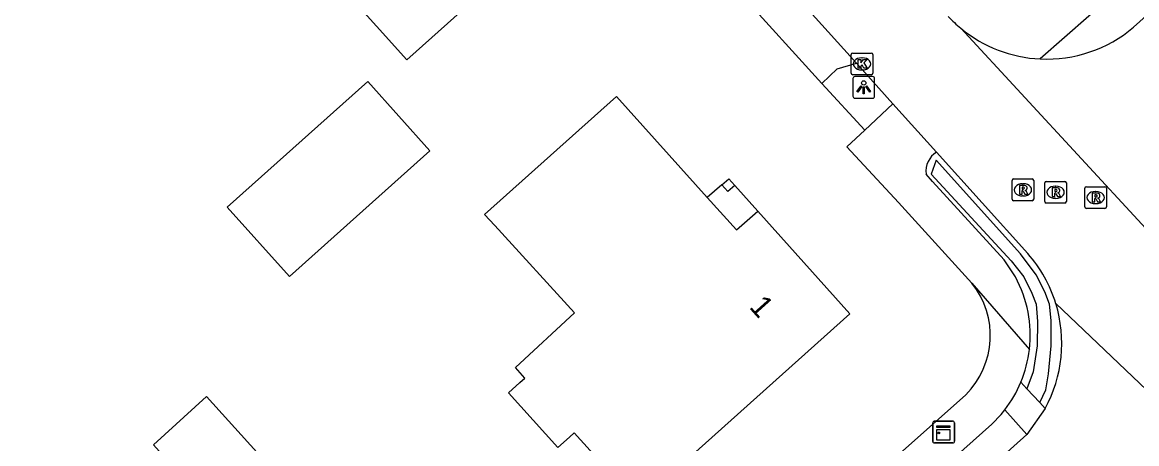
# Model space of a CAD drawing. Extents: x 163268 to 164360, y 381529 to 382285.
# Drawn here: x 163951.8 to 164003, y 381738.3 to 381757.6 of the extents above; entities that cross this region are included whole.
import ezdxf

# ---------------------------------------------------------------- set-up
doc = ezdxf.new("R2010")
doc.units = 0
for name, color, linetype in [('IMGEO_Haag', 7, 'Continuous'), ('IMGEO_Kast', 7, 'Continuous'), ('IMGEO_Kolk', 7, 'Continuous'), ('IMGEO_Lichtpunt', 7, 'Continuous'), ('IMGEO_Pand', 7, 'Continuous'), ('IMGEO_Pand_nummerreeks', 7, 'Continuous'), ('IMGEO_Pand_overbouw', 7, 'Continuous'), ('IMGEO_Rijbaan_lokaal_open', 7, 'Continuous'), ('IMGEO_Rioolput', 7, 'Continuous'), ('IMGEO_Voetpad_halfverhard', 7, 'Continuous'), ('IMGEO_Voetpad_open', 7, 'Continuous')]:
    doc.layers.add(name, color=color, linetype=linetype)

msp = doc.modelspace()

# ---------------------------------------------------------------- linework, layer by layer
at = {"layer": 'IMGEO_Haag'}
msp.add_lwpolyline([(163998.511, 381740.158), (163998.792, 381740.742), (163998.918, 381741.476), (163999.044, 381742.778), (163999.044, 381743.932), (163998.96, 381744.688), (163998.74, 381745.26), (163998.341, 381746.036), (163997.623, 381747.001), (163993.75, 381751.311), (163993.518, 381750.663), (163997.204, 381746.68), (163997.774, 381745.947), (163998.152, 381745.191), (163998.351, 381744.688), (163998.414, 381743.89), (163998.393, 381742.778), (163998.205, 381741.581), (163997.921, 381740.797)], dxfattribs=at)
at = {"layer": 'IMGEO_Kast'}
for p, q in [((163993.592, 381738.378), (163993.592, 381739.219)), ((163993.592, 381739.219), (163993.592, 381738.378)), ((163993.667, 381739.303), (163994.508, 381739.303)), ((163994.508, 381739.303), (163993.667, 381739.303)), ((163994.592, 381739.228), (163994.592, 381738.387)), ((163994.592, 381738.387), (163994.592, 381739.228)), ((163994.517, 381738.303), (163993.676, 381738.303)), ((163993.676, 381738.303), (163994.517, 381738.303))]:
    msp.add_line(p, q, dxfattribs=at)
for points in [[(163993.787, 381739.093), (163994.387, 381739.093), (163994.387, 381739.008), (163993.787, 381739.008), (163993.787, 381739.093)], [(163993.787, 381738.918), (163994.387, 381738.918), (163994.387, 381738.429), (163993.787, 381738.429), (163993.787, 381738.918)]]:
    msp.add_lwpolyline(points, dxfattribs=at)
msp.add_circle((163993.871, 381738.767), 0.0377, dxfattribs=at)
for centre, start, end in [((163993.67, 381739.225), 92.4484, 184.2845), ((163993.67, 381739.225), 92.4484, 184.2845), ((163994.514, 381739.225), 2.4484, 94.2845), ((163994.514, 381739.225), 2.4484, 94.2845), ((163993.67, 381738.381), 182.4484, 274.2845), ((163993.67, 381738.381), 182.4484, 274.2845), ((163994.514, 381738.381), 272.4484, 4.2845), ((163994.514, 381738.381), 272.4484, 4.2845)]:
    msp.add_arc(centre, 0.0779, start, end, dxfattribs=at)
at = {"layer": 'IMGEO_Kolk'}
for p, q in [((163989.84, 381755.309), (163989.84, 381756.161)), ((163989.915, 381756.235), (163990.767, 381756.235)), ((163990.328, 381756.015), (163990.353, 381756.015)), ((163990.841, 381756.161), (163990.841, 381755.309)), ((163990.351, 381755.455), (163990.326, 381755.455)), ((163990.767, 381755.235), (163989.915, 381755.235))]:
    msp.add_line(p, q, dxfattribs=at)
for points in [[(163989.84, 381755.309), (163989.84, 381756.161)], [(163989.915, 381756.235), (163990.767, 381756.235)], [(163990.161, 381755.935), (163990.284, 381755.935), (163990.284, 381755.784), (163990.414, 381755.935), (163990.578, 381755.935), (163990.432, 381755.784), (163990.585, 381755.535), (163990.433, 381755.535), (163990.348, 381755.699), (163990.284, 381755.632), (163990.284, 381755.535), (163990.161, 381755.535), (163990.161, 381755.935)], [(163990.841, 381756.161), (163990.841, 381755.309)], [(163990.767, 381755.235), (163989.915, 381755.235)]]:
    msp.add_lwpolyline(points, dxfattribs=at)
for centre, start, end in [((163989.917, 381756.159), 91.552, 178.448), ((163989.917, 381756.159), 91.552, 178.448), ((163990.765, 381756.159), 1.552, 88.448), ((163990.765, 381756.159), 1.552, 88.448), ((163989.917, 381755.311), 181.552, 268.448), ((163989.917, 381755.311), 181.552, 268.448), ((163990.765, 381755.311), 271.552, 358.448), ((163990.765, 381755.311), 271.552, 358.448)]:
    msp.add_arc(centre, 0.0765, start, end, dxfattribs=at)
for centre, major_axis, ratio, start_param, end_param in [((163990.327, 381755.735), (-0.387, 0.002), 0.722429, 4.712389, 7.853982), ((163990.352, 381755.735), (-0.39, 0.002), 0.717154, 1.570796, 4.712389)]:
    msp.add_ellipse(centre, major_axis=major_axis, ratio=ratio, start_param=start_param, end_param=end_param, dxfattribs=at)
at = {"layer": 'IMGEO_Lichtpunt'}
for p, q in [((163989.926, 381755.06), (163989.926, 381754.253)), ((163989.926, 381755.06), (163989.926, 381754.253)), ((163990.828, 381755.155), (163990.02, 381755.155)), ((163990.828, 381755.155), (163990.02, 381755.155)), ((163990.922, 381754.253), (163990.922, 381755.06)), ((163990.922, 381754.253), (163990.922, 381755.06)), ((163990.02, 381754.159), (163990.828, 381754.159)), ((163990.02, 381754.159), (163990.828, 381754.159))]:
    msp.add_line(p, q, dxfattribs=at)
for points in [[(163990.3, 381754.724), (163990.339, 381754.696), (163990.151, 381754.434), (163990.113, 381754.461), (163990.3, 381754.724)], [(163990.402, 381754.676), (163990.449, 381754.676), (163990.449, 381754.354), (163990.402, 381754.354), (163990.402, 381754.676)], [(163990.512, 381754.696), (163990.55, 381754.723), (163990.737, 381754.461), (163990.698, 381754.433), (163990.512, 381754.696)]]:
    msp.add_lwpolyline(points, dxfattribs=at)
msp.add_circle((163990.425, 381754.858), 0.0994, dxfattribs=at)
for centre, start, end in [((163990.02, 381755.06), 90, 180), ((163990.02, 381755.06), 90, 180), ((163990.828, 381755.06), 0, 90), ((163990.828, 381755.06), 0, 90), ((163990.02, 381754.253), 180, 270), ((163990.02, 381754.253), 180, 270), ((163990.828, 381754.253), 270, 0), ((163990.828, 381754.253), 270, 360)]:
    msp.add_arc(centre, 0.0946, start, end, dxfattribs=at)
at = {"layer": 'IMGEO_Pand'}
for points in [[(163965.246, 381760.582), (163963.764, 381759.239), (163959.258, 381764.212), (163960.741, 381765.555), (163960.075, 381766.289), (163965.567, 381771.211), (163974.889, 381760.835), (163969.419, 381755.929), (163965.246, 381760.582)], [(163961.17, 381749.144), (163967.63, 381754.927), (163970.487, 381751.735), (163964.028, 381745.953), (163961.17, 381749.144)], [(163979.064, 381754.234), (163983.233, 381749.598), (163984.57, 381748.111), (163985.554, 381748.969), (163989.791, 381744.248), (163980.063, 381735.515), (163977.118, 381738.774), (163976.899, 381738.577), (163976.361, 381738.091), (163974.092, 381740.608), (163974.62, 381741.084), (163974.849, 381741.291), (163974.416, 381741.778), (163977.13, 381744.283), (163973.47, 381748.297), (163972.999, 381748.813), (163979.064, 381754.234)], [(163983.902, 381750.181), (163984.219, 381750.457), (163984.499, 381750.144), (163984.183, 381749.868), (163983.902, 381750.181)], [(163957.785, 381738.222), (163960.225, 381740.447), (163964.847, 381735.323), (163965.172, 381735.604), (163965.852, 381734.818), (163965.574, 381734.523), (163966.36, 381733.631), (163963.849, 381731.446), (163957.785, 381738.222)]]:
    msp.add_lwpolyline(points, dxfattribs=at)
at = {"layer": 'IMGEO_Pand_overbouw'}
msp.add_lwpolyline([(163984.499, 381750.144), (163984.183, 381749.868), (163983.902, 381750.181), (163983.233, 381749.598), (163984.57, 381748.111), (163985.554, 381748.969)], close=True, dxfattribs=at)
at = {"layer": 'IMGEO_Rijbaan_lokaal_open'}
for points in [[(164002.826, 381757.42), (164010.255, 381764.1)], [(163985.739, 381760.594), (163990.087, 381755.766)], [(164005.983, 381745.357), (163994.884, 381757.372)], [(163990.087, 381755.766), (163991.765, 381753.902)], [(163993.771, 381751.675), (163991.765, 381753.902)], [(163993.771, 381751.675), (163997.969, 381747.012)], [(163999.252, 381744.71), (164008.883, 381735.535)], [(163998.759, 381739.889), (163997.915, 381738.698)], [(163997.915, 381738.698), (163942.403, 381688.848)]]:
    msp.add_lwpolyline(points, dxfattribs=at)
for centre, radius, start, end in [((163998.916, 381762.242), 6.323, 223.212, 230.3774), ((163998.831, 381762.16), 6.205, 230.5017, 267.2972), ((163998.826, 381762.149), 6.194, 267.334, 310.224), ((163993.259, 381742.878), 6.266, 16.9941, 41.2714), ((163993.273, 381742.886), 6.251, 331.3545, 16.9679)]:
    msp.add_arc(centre, radius, start, end, dxfattribs=at)
at = {"layer": 'IMGEO_Rioolput'}
for p, q in [((163997.238, 381749.518), (163997.238, 381750.37)), ((163997.313, 381750.444), (163998.165, 381750.444)), ((163997.726, 381750.224), (163997.751, 381750.224)), ((163998.239, 381750.37), (163998.239, 381749.518)), ((163998.739, 381749.407), (163998.739, 381750.259)), ((163998.814, 381750.333), (163999.666, 381750.333)), ((163999.74, 381750.259), (163999.74, 381749.407)), ((163997.749, 381749.664), (163997.724, 381749.664)), ((163999.227, 381750.113), (163999.252, 381750.113)), ((164000.581, 381749.162), (164000.581, 381750.014)), ((164000.656, 381750.088), (164001.508, 381750.088)), ((164001.069, 381749.868), (164001.094, 381749.868)), ((164001.582, 381750.014), (164001.582, 381749.162)), ((163998.165, 381749.444), (163997.313, 381749.444)), ((163999.666, 381749.333), (163998.814, 381749.333)), ((163999.25, 381749.553), (163999.225, 381749.553)), ((164001.092, 381749.308), (164001.067, 381749.308)), ((164001.508, 381749.088), (164000.656, 381749.088))]:
    msp.add_line(p, q, dxfattribs=at)
for points in [[(163997.238, 381749.518), (163997.238, 381750.37)], [(163997.313, 381750.444), (163998.165, 381750.444)], [(163997.827, 381750.142), (163997.575, 381750.144), (163997.575, 381749.744)], [(163998.239, 381750.37), (163998.239, 381749.518)], [(163998.739, 381749.407), (163998.739, 381750.259)], [(163998.814, 381750.333), (163999.666, 381750.333)], [(163999.74, 381750.259), (163999.74, 381749.407)], [(163997.575, 381749.744), (163997.699, 381749.744), (163997.699, 381749.906), (163997.71, 381749.906)], [(163997.753, 381750.063), (163997.699, 381750.063), (163997.699, 381749.982)], [(163997.699, 381749.982), (163997.751, 381749.982)], [(163997.757, 381749.877), (163997.828, 381749.744), (163997.968, 381749.744), (163997.903, 381749.87)], [(163999.328, 381750.031), (163999.076, 381750.033), (163999.076, 381749.633)], [(163999.076, 381749.633), (163999.2, 381749.633), (163999.2, 381749.795), (163999.211, 381749.795)], [(163999.254, 381749.952), (163999.2, 381749.952), (163999.2, 381749.871)], [(163999.2, 381749.871), (163999.252, 381749.871)], [(163999.258, 381749.766), (163999.329, 381749.633), (163999.469, 381749.633), (163999.404, 381749.759)], [(164000.581, 381749.162), (164000.581, 381750.014)], [(164000.656, 381750.088), (164001.508, 381750.088)], [(164001.17, 381749.786), (164000.918, 381749.788), (164000.918, 381749.388)], [(164001.096, 381749.707), (164001.042, 381749.707), (164001.042, 381749.626)], [(164001.042, 381749.626), (164001.094, 381749.626)], [(164001.582, 381750.014), (164001.582, 381749.162)], [(163998.165, 381749.444), (163997.313, 381749.444)], [(163999.666, 381749.333), (163998.814, 381749.333)], [(164000.918, 381749.388), (164001.042, 381749.388), (164001.042, 381749.55), (164001.053, 381749.55)], [(164001.1, 381749.521), (164001.171, 381749.388), (164001.311, 381749.388), (164001.246, 381749.514)], [(164001.508, 381749.088), (164000.656, 381749.088)]]:
    msp.add_lwpolyline(points, dxfattribs=at)
for centre, radius, start, end in [((163997.315, 381750.368), 0.0765, 91.552, 178.448), ((163997.315, 381750.368), 0.0765, 91.552, 178.448), ((163997.826, 381750.032), 0.109, 350.3612, 89.416), ((163998.163, 381750.368), 0.0765, 1.552, 88.448), ((163998.163, 381750.368), 0.0765, 1.552, 88.448), ((163998.816, 381750.257), 0.0765, 91.552, 178.448), ((163998.816, 381750.257), 0.0765, 91.552, 178.448), ((163999.664, 381750.257), 0.0765, 1.552, 88.448), ((163999.664, 381750.257), 0.0765, 1.552, 88.448), ((163997.709, 381749.853), 0.0533, 26.0293, 88.6989), ((163997.735, 381750.171), 0.19, 274.7715, 282.9687), ((163997.759, 381749.967), 0.0964, 77.0061, 93.1865), ((163997.773, 381750.024), 0.0378, 276.6634, 79.6772), ((163997.824, 381750.032), 0.112, 277.5842, 350.9817), ((163997.808, 381749.817), 0.108, 29.5134, 73.7905), ((163999.21, 381749.742), 0.0533, 26.0293, 88.6989), ((163999.236, 381750.06), 0.19, 274.7715, 282.9687), ((163999.26, 381749.856), 0.0964, 77.0061, 93.1865), ((163999.274, 381749.913), 0.0378, 276.6634, 79.6772), ((163999.327, 381749.921), 0.109, 350.3612, 89.416), ((163999.325, 381749.921), 0.112, 277.5842, 350.9817), ((163999.309, 381749.706), 0.108, 29.5134, 73.7905), ((164000.658, 381750.012), 0.0765, 91.552, 178.448), ((164000.658, 381750.012), 0.0765, 91.552, 178.448), ((164001.078, 381749.815), 0.19, 274.7715, 282.9687), ((164001.102, 381749.611), 0.0964, 77.0061, 93.1865), ((164001.116, 381749.668), 0.0378, 276.6634, 79.6772), ((164001.169, 381749.676), 0.109, 350.3612, 89.416), ((164001.167, 381749.676), 0.112, 277.5842, 350.9817), ((164001.506, 381750.012), 0.0765, 1.552, 88.448), ((164001.506, 381750.012), 0.0765, 1.552, 88.448), ((163997.315, 381749.52), 0.0765, 181.552, 268.448), ((163997.315, 381749.52), 0.0765, 181.552, 268.448), ((163998.163, 381749.52), 0.0765, 271.552, 358.448), ((163998.163, 381749.52), 0.0765, 271.552, 358.448), ((163998.816, 381749.409), 0.0765, 181.552, 268.448), ((163998.816, 381749.409), 0.0765, 181.552, 268.448), ((163999.664, 381749.409), 0.0765, 271.552, 358.448), ((163999.664, 381749.409), 0.0765, 271.552, 358.448), ((164000.658, 381749.164), 0.0765, 181.552, 268.448), ((164000.658, 381749.164), 0.0765, 181.552, 268.448), ((164001.052, 381749.497), 0.0533, 26.0293, 88.6989), ((164001.151, 381749.461), 0.108, 29.5134, 73.7905), ((164001.506, 381749.164), 0.0765, 271.552, 358.448), ((164001.506, 381749.164), 0.0765, 271.552, 358.448)]:
    msp.add_arc(centre, radius, start, end, dxfattribs=at)
for centre, major_axis, ratio, start_param, end_param in [((163997.725, 381749.944), (-0.387, 0.002), 0.722429, 4.712389, 7.853982), ((163997.75, 381749.944), (-0.39, 0.002), 0.717154, 1.570796, 4.712389), ((163999.226, 381749.833), (-0.387, 0.002), 0.722429, 4.712389, 7.853982), ((163999.251, 381749.833), (-0.39, 0.002), 0.717154, 1.570796, 4.712389), ((164001.068, 381749.588), (-0.387, 0.002), 0.722429, 4.712389, 7.853982), ((164001.093, 381749.588), (-0.39, 0.002), 0.717154, 1.570796, 4.712389)]:
    msp.add_ellipse(centre, major_axis=major_axis, ratio=ratio, start_param=start_param, end_param=end_param, dxfattribs=at)
at = {"layer": 'IMGEO_Voetpad_halfverhard'}
msp.add_lwpolyline([(163990.472, 381752.694), (163988.491, 381754.827)], dxfattribs=at)
at = {"layer": 'IMGEO_Voetpad_open'}
for points in [[(164009.602, 381765.882), (164007.005, 381763.532), (164001.892, 381758.93), (163998.538, 381755.962)], [(163988.491, 381754.827), (163984.719, 381759.012)], [(163988.491, 381754.827), (163989.204, 381755.509), (163990.087, 381755.766)], [(163991.765, 381753.902), (163990.472, 381752.694)], [(163995.387, 381745.649), (163992.019, 381749.355), (163989.649, 381751.925), (163990.472, 381752.694)], [(163997.397, 381745.94), (163996.882, 381746.726), (163993.58, 381750.326), (163993.292, 381750.672)], [(163995.387, 381745.649), (163998.038, 381742.606)], [(163997.643, 381741.098), (163997.921, 381740.797)], [(163907.846, 381662.609), (163917.878, 381671.183), (163917.751, 381671.321), (163960.431, 381709.666), (163995.111, 381740.522)], [(163997.921, 381740.797), (163998.511, 381740.158)], [(163998.511, 381740.158), (163998.759, 381739.889)], [(163942.403, 381688.848), (163941.316, 381690.061), (163942.506, 381691.118), (163996.309, 381739.168), (163996.732, 381739.613), (163996.909, 381739.831)], [(163997.915, 381738.698), (163996.909, 381739.831)]]:
    msp.add_lwpolyline(points, dxfattribs=at)
for centre, radius, start, end in [((163994.298, 381750.808), 1.015, 121.2647, 187.6801), ((163992.41, 381743.238), 3.831, 314.8412, 38.996), ((163992.454, 381743.261), 5.623, 353.3104, 28.4556), ((163992.459, 381743.262), 5.618, 337.3467, 353.2971), ((163992.528, 381743.215), 5.536, 322.3161, 337.5147)]:
    msp.add_arc(centre, radius, start, end, dxfattribs=at)

# ---------------------------------------------------------------- texts
at = {"layer": 'IMGEO_Pand_nummerreeks'}
msp.add_text('1', height=1, rotation=311.9059, dxfattribs=at).set_placement((163985.123, 381744.538))

doc.saveas('drawing.dxf')
